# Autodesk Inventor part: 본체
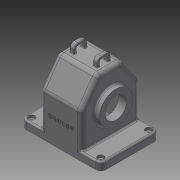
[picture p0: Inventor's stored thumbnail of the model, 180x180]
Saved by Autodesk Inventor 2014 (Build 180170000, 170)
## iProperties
Created: 2016-12
Part Number: 본체
Material: 일반
Document SubType Name: Modeling
Designer: USER
Density: 1 g/cm^3
Appearance: 기본값
Author: USER
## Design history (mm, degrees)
sketch "스케치1"
  geometry: L1 (110, 0)-(110, -65); L2 (110, -65)-(0, -65); L3 (0, -65)-(0, 0); L4 (0, 0)-(31.509, 45); L5 (31.509, 45)-(78.491, 45); L6 (78.491, 45)-(110, 0)
  constraints: 12 end point, 2 horizontal alignment, 2 vertical alignment, 1 equal length, 1 parallel, 1 perpendicular
  dimensions: "d0" = 65 distance of L1.start L1.end; "d1" = 35 deg angle of L3 L4; "d2" = 35 deg angle of L1 L6; "d3" = 110 distance between parallel lines of L2 L5; "d4" = 110 distance of L1.end L2.end
extrude "돌출1" new body sketch "스케치1" distance "d5" = 77; taper "d6" = 0 deg
fillet "모깎기1" dims "d7" = 10
node "작업 평면1"
sketch "스케치5"
  geometry: L1 (-40.736, 28.523)-(-2.583, 1.808) reference; L2 (-45, 73.285)-(-45, 36.715) reference; L3 (-2.583, 108.192)-(-40.736, 81.477) reference; L4 (65, 110)-(3.153, 110) reference; L5 (3.153, 0)-(65, 0) reference; L6 (110.135, 5)-(3.153, 5); L7 (0.285, 5.904)-(-37.868, 32.619); L8 (-40, 36.715)-(-40, 73.285); L9 (-37.868, 77.381)-(0.285, 104.096); L10 (3.153, 105)-(110.135, 105); L11 (110.135, 5)-(110.135, 105); A1 r 10 centre (-35, 36.715) between (-45, 36.715) and (-40.736, 28.523) reference; A2 r 10 centre (-35, 73.285) between (-40.736, 81.477) and (-45, 73.285) reference; A3 r 10 centre (3.153, 100) between (3.153, 110) and (-2.583, 108.192) reference; A4 r 10 centre (3.153, 10) between (-2.583, 1.808) and (3.153, 0) reference; A5 r 5 centre (3.153, 10) between (0.285, 5.904) and (3.153, 5); A6 r 5 centre (-35, 36.715) between (-40, 36.715) and (-37.868, 32.619); A7 r 5 centre (-35, 73.285) between (-37.868, 77.381) and (-40, 73.285); A8 r 5 centre (3.153, 100) between (3.153, 105) and (0.285, 104.096); 1 further point
  constraints: 12 end point, 8 point on circle, 4 centre point, 1 perpendicular, 8 other
  dimensions: "d26" = 5 distance between parallel lines of L2 L8; "d29" = 150.13503 distance between parallel lines of L8 L11
extrude "돌출5" cut sketch "스케치5" stored distance "d27" = 67; taper "d28" = 0 deg
node "작업 평면2"
fillet "모깎기2" dims "d8" = 8
sketch "스케치2"
  geometry: L1 (0, 0)-(0, 94) reference; L2 (-8, 102)-(-69, 102) reference; L3 (-8, -8)-(-69, -8) reference; L4 (36.5, -8)-(-113.5, -8); L5 (-113.5, -8)-(-113.5, 102); L6 (-113.5, 102)-(36.5, 102); L7 (36.5, 102)-(36.5, -8); 7 further points
  constraints: 8 end point, 6 midpoint, 2 coincident, 2 parallel, 1 horizontal, 1 horizontal alignment, 1 perpendicular
  dimensions: "d10" = 110 distance of L6.end L4.start; "d11" = 150 distance of L5.end L6.end
extrude "돌출2" join sketch "스케치2" distance "d12" = 15; taper "d13" = 0 deg
fillet "모깎기3" dims "d14" = 10
fillet "모깎기4" dims "d15" = 3
fillet "모깎기5" dims "d16" = 3
sketch "스케치3"
  geometry: L1 (-37, 36.715)-(-37, 73.285) reference; L2 (80, 100)-(80, 10) reference; C1 r 31 at (15, 55); 2 further points
  constraints: 1 centre point, 1 horizontal alignment, 1 midpoint
  dimensions: "d17" = 62 diameter of C1; "d18" = 65 distance from line of L2 C1.centre
extrude "돌출3" join sketch "스케치3" distance "d19" = 10; taper "d20" = 0 deg
sketch "스케치4"
  geometry: L1 (37, 73.285)-(37, 36.715) reference; L2 (-80, 10)-(-80, 100) reference; C1 r 37.5 at (-15, 55); 2 further points
  constraints: 1 centre point, 1 horizontal alignment, 1 midpoint
  dimensions: "d21" = 75 diameter of C1; "d22" = 65 distance from line of C1.centre L2
extrude "돌출4" join sketch "스케치4" distance "d23" = 5; taper "d24" = 0 deg
fillet "모깎기6" dims "d25" = 3
sketch "스케치6"
  geometry: L1 (65, 5)-(3.153, 5) reference; L2 (3.153, 105)-(65, 105) reference; L3 (65, 5)-(87.352, 5); L4 (87.352, 5)-(87.352, 105); L5 (87.352, 105)-(65, 105); L6 (65, 5)-(65, 105); 1 further point
  constraints: 8 end point, 2 parallel, 2 perpendicular
  dimensions: "d30" = 22.35191 distance between parallel lines of L4 L6
extrude "돌출6" cut sketch "스케치6" stored distance "d31" = 67; taper "d32" = 0 deg
fillet "모깎기7" dims "d33" = 3
node "작업 평면4"
  node "작업 평면3"
sketch "스케치7"
  geometry: L1 (82.583, 98.192)-(120.736, 71.477) reference; L2 (120.736, 18.523)-(82.583, -8.192) reference; L3 (125, 57.5)-(140, 57.5); L4 (140, 57.5)-(140, 32.5); L5 (140, 32.5)-(125, 32.5); L6 (125, 52.5)-(135, 52.5); L7 (135, 52.5)-(135, 37.5); L8 (135, 37.5)-(125, 37.5); L9 (125, 63.285)-(125, 26.715) reference; L10 (125, 57.5)-(125, 52.5); L11 (125, 37.5)-(125, 32.5); A1 r 10 centre (115, 63.285) between (125, 63.285) and (120.736, 71.477) reference; A2 r 10 centre (115, 26.715) between (120.736, 18.523) and (125, 26.715) reference; 4 further points
  constraints: 16 end point, 4 vertical alignment, 3 midpoint, 2 collinear, 2 horizontal, 2 horizontal alignment, 2 parallel, 2 perpendicular
  dimensions: "d36" = 25 distance between parallel lines of L5 L3; "d37" = 15 distance between parallel lines of L8 L6; "d38" = 15 distance of L4.end L5.end; "d39" = 10 distance between parallel lines of L9 L7
extrude "돌출7" join sketch "스케치7" distance "d40" = 8; taper "d41" = 0 deg
fillet "모깎기8" dims "d42" = 8
fillet "모깎기9" dims "d43" = 3
fillet "모깎기10" dims "d44" = 1
fillet "모깎기11" dims "d45" = 1
sketch "스케치8"
  geometry: C1 r 31 at (0, 0) reference; C2 r 20 at (0, 0); 1 further point
  constraints: 1 centre point, 1 coincident
  dimensions: "d46" = 40 diameter of C2
extrude "돌출8" cut sketch "스케치8" stored distance "d47" = 8; taper "d48" = 0 deg
node "작업 평면5"
sketch "스케치9"
  geometry: L1 (-13, -31.847)-(-13, 8.153) reference; L2 (-13, -11.847)-(67.573, -11.847); L3 (-3, 39.3)-(-3, 1.147) reference; L4 (-3, 0)-(-3, -76.847) reference; L5 (11, 8.153)-(11, 15.153); L6 (11, 15.153)-(-3, 29.153); L7 (-3, 8.153)-(11, 8.153); L8 (-3, 8.153)-(-3, 29.153); 1 further point
  constraints: 10 end point, 2 perpendicular, 2 point on line, 1 collinear, 1 horizontal alignment, 1 midpoint, 1 parallel, 1 vertical alignment
  dimensions: "d49" = 40 diameter of L7 L2; "d50" = 54 diameter of L5.end L2; "d51" = 45 deg angle of L5 L6; "d52" = 24 distance between parallel lines of L5 L1
revolve "회전1" sketch "스케치9" stored, may be unused: angle "d53" = 90 deg
sketch "스케치10" dims "d54" = 52
  geometry: C1 r 20 at (0, 0) reference; C2 r 31 at (0, 0) reference; 3 further points
  constraints: 2 horizontal alignment, 1 coincident, 2 other
hole "구멍1" sketch "스케치10" at (-26, 0) diameter "d55" = 2.459; stored, may be unused: countersink angle "d59" = 90 deg, drill point angle "d61" = 118 deg; dims "d56" = 6, "d57" = 4, "d58" = 2, "d60" = 8
sketch "스케치11" dims "d65" = 58
  geometry: C1 r 20 at (0, 0) reference; C2 r 37.5 at (0, 0) reference; 3 further points
  constraints: 2 horizontal alignment, 1 coincident, 2 other
hole "구멍2" sketch "스케치11" at (29, 0) diameter "d66" = 2.459; stored, may be unused: countersink angle "d70" = 90 deg, drill point angle "d72" = 118 deg; dims "d67" = 6, "d68" = 4, "d69" = 2, "d71" = 8
sketch "스케치12"
  geometry: A1 r 7 centre (103.5, 2) between (103.5, -5) and (110.5, 2) reference; A2 r 7 centre (103.5, 92) between (110.5, 92) and (103.5, 99) reference; 3 further points
  constraints: 2 coincident
hole "구멍3" sketch "스케치12" at (103.5, 92), (103.5, 2) diameter "d76" = 5; stored, may be unused: countersink angle "d80" = 90 deg, drill point angle "d82" = 118 deg; dims "d77" = 6, "d78" = 12, "d79" = 5, "d81" = 8
sketch "스케치13"
  geometry: L1 (95.5, -76.847)-(-34.5, -76.847) reference; L2 (-8, 0)-(-8, -58.847) reference; 2 further points
  constraints: 1 other
  dimensions: "d83" = 38.5 distance from line of point (30.5, -31.847) L2; "d84" = 45 distance from line of L1 point (30.5, -31.847)
feature "엠보싱1" sketch "스케치13" dims "d85" = 0.5, "d86" = 0
node "솔리드1"
mirror "대칭1"
pattern_circular "원형 패턴1" dims angle "d63" = 360 deg
pattern_circular "원형 패턴2" dims angle "d74" = 360 deg
mirror "대칭2"
other parameters: "d34" = -75, "d35" = 26
